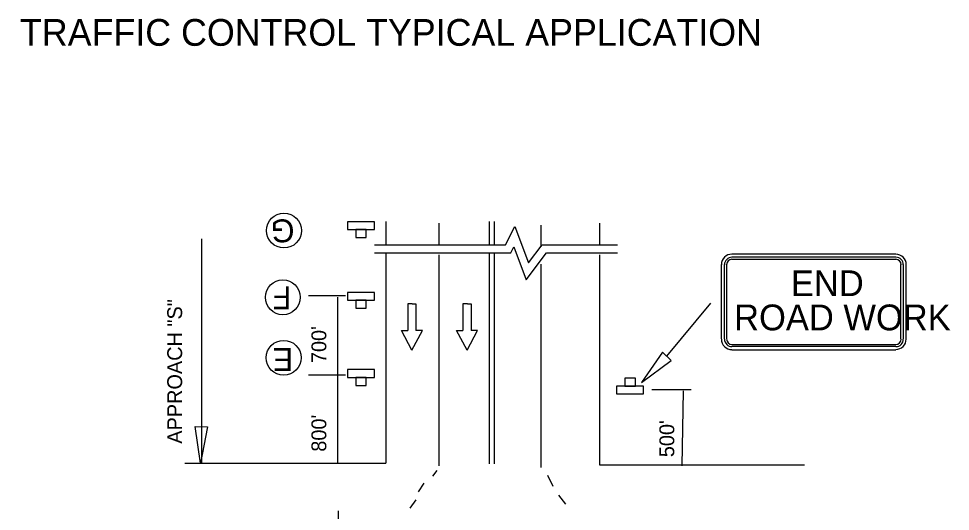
# Model space of a CAD drawing. Extents: x 1531.4 to 1538.6, y 1529.6 to 1539.6.
# Drawn here: x 1533.692 to 1537.45, y 1537.609 to 1539.597 of the extents above; entities that cross this region are included whole.
import ezdxf

# ---------------------------------------------------------------- set-up
doc = ezdxf.new("R2010")
doc.units = 0
for name, color, linetype in [('DETL-DIMS', 7, 'Continuous'), ('DETL-LINE', 7, 'Continuous'), ('DETL-NOTE', 7, 'Continuous'), ('DETL-TITL', 7, 'Continuous'), ('USER-BORD', 7, 'Continuous')]:
    doc.layers.add(name, color=color, linetype=linetype)

# ---------------------------------------------------------------- blocks, each defined once
blk = doc.blocks.new('DIR2')
at = {"layer": 'USER-BORD'}
for p, q in [((0, 0.0012), (-0.0342, -0.0477)), ((0, 0.0012), (0.0342, -0.0477)), ((-0.0342, -0.0477), (-0.0132, -0.0477)), ((-0.0132, -0.1133), (-0.0132, -0.0477)), ((0.0342, -0.0477), (0.0132, -0.0477)), ((0.0132, -0.1133), (0.0132, -0.0477)), ((-0.0011, -0.1133), (-0.0132, -0.1133)), ((-0.0011, -0.1133), (0.0011, -0.1133)), ((0.0011, -0.1133), (0.0132, -0.1133))]:
    blk.add_line(p, q, dxfattribs=at)

msp = doc.modelspace()

# ---------------------------------------------------------------- linework, layer by layer
at = {"layer": 'DETL-DIMS'}
for p, q in [((1534.4291, 1538.7082), (1534.4291, 1537.8015)), ((1535.0111, 1538.4782), (1534.8607, 1538.4782)), ((1534.9782, 1538.4735), (1534.9782, 1537.8006)), ((1536.3068, 1538.2347), (1536.4846, 1538.4491)), ((1535.0111, 1538.1583), (1534.8607, 1538.1583)), ((1536.2462, 1538.1008), (1536.4053, 1538.1008)), ((1536.3723, 1538.0957), (1536.3672, 1537.7929))]:
    msp.add_line(p, q, dxfattribs=at)
for points in [[(1536.3245, 1538.2176), (1536.2891, 1538.2518), (1536.2044, 1538.1282)], [(1534.4042, 1537.9511), (1534.4534, 1537.9501), (1534.4259, 1537.8029)]]:
    msp.add_lwpolyline(points, close=True, dxfattribs=at)
at = {"layer": 'DETL-LINE'}
for p, q in [((1535.1727, 1538.7783), (1535.1727, 1538.6847)), ((1535.3872, 1538.771), (1535.3872, 1538.6847)), ((1535.5897, 1538.7783), (1535.5897, 1538.6847)), ((1535.6101, 1538.7783), (1535.6101, 1538.6847)), ((1536.0344, 1538.771), (1536.0344, 1538.6847)), ((1535.798, 1538.7637), (1535.798, 1538.6765)), ((1535.1727, 1538.6515), (1535.1727, 1537.9889)), ((1535.3872, 1538.6442), (1535.3872, 1537.7928)), ((1535.5897, 1538.6515), (1535.5897, 1537.9889)), ((1535.6101, 1538.6515), (1535.6101, 1537.9889)), ((1536.0344, 1538.6442), (1536.0344, 1537.9816)), ((1537.2302, 1538.6464), (1536.5692, 1538.6464)), ((1537.2302, 1538.6344), (1536.5692, 1538.6344)), ((1536.5692, 1538.6264), (1537.2302, 1538.6264)), ((1537.2302, 1538.6344), (1537.2302, 1538.6344)), ((1535.798, 1538.6059), (1535.798, 1537.7856)), ((1536.5262, 1538.6044), (1536.5262, 1538.3044)), ((1536.5392, 1538.3044), (1536.5392, 1538.6044)), ((1536.5472, 1538.6044), (1536.5472, 1538.3044)), ((1537.2512, 1538.3044), (1537.2512, 1538.6044)), ((1537.2602, 1538.6044), (1537.2602, 1538.3044)), ((1537.2722, 1538.3044), (1537.2722, 1538.6044)), ((1536.5692, 1538.2824), (1537.2302, 1538.2824)), ((1536.5694, 1538.2821), (1536.5696, 1538.2827)), ((1537.2302, 1538.2744), (1536.5692, 1538.2744)), ((1536.5692, 1538.2604), (1537.2302, 1538.2604)), ((1535.1727, 1537.9974), (1535.1727, 1537.8033)), ((1535.5897, 1537.9974), (1535.5897, 1537.8002)), ((1535.6101, 1537.9974), (1535.6101, 1537.8002)), ((1536.0344, 1537.9901), (1536.0344, 1537.796)), ((1534.3621, 1537.8033), (1535.1727, 1537.8033)), ((1536.0344, 1537.796), (1536.862, 1537.796)), ((1535.3791, 1537.7744), (1535.3616, 1537.7511)), ((1535.8253, 1537.7544), (1535.8472, 1537.7106)), ((1535.3267, 1537.722), (1535.3035, 1537.6871)), ((1535.2938, 1537.656), (1535.2705, 1537.6211)), ((1535.869, 1537.6742), (1535.8981, 1537.6378)), ((1534.9823, 1536.8051), (1534.9823, 1537.6108))]:
    msp.add_line(p, q, dxfattribs=at)
for points in [[(1535.127, 1538.7459), (1535.127, 1538.7772), (1535.0179, 1538.7772), (1535.0179, 1538.7459)], [(1535.0515, 1538.7134), (1535.0935, 1538.7134), (1535.0935, 1538.7459), (1535.0515, 1538.7459)], [(1535.127, 1538.4609), (1535.127, 1538.4922), (1535.0179, 1538.4922), (1535.0179, 1538.4609)], [(1535.0515, 1538.4284), (1535.0935, 1538.4284), (1535.0935, 1538.4609), (1535.0515, 1538.4609)], [(1535.127, 1538.1496), (1535.127, 1538.1809), (1535.0179, 1538.1809), (1535.0179, 1538.1496)], [(1535.0515, 1538.1171), (1535.0935, 1538.1171), (1535.0935, 1538.1496), (1535.0515, 1538.1496)], [(1536.1797, 1538.1468), (1536.1377, 1538.1468), (1536.1377, 1538.1143), (1536.1797, 1538.1143)], [(1536.1042, 1538.1143), (1536.1042, 1538.083), (1536.2132, 1538.083), (1536.2132, 1538.1143)]]:
    msp.add_lwpolyline(points, close=True, dxfattribs=at)
for points in [[(1535.1273, 1538.6847), (1535.6564, 1538.6847), (1535.6935, 1538.7579), (1535.7489, 1538.6114), (1535.8043, 1538.6847), (1536.1074, 1538.6847)], [(1535.1273, 1538.6515), (1535.6768, 1538.6515), (1535.6891, 1538.6757), (1535.739, 1538.5434), (1535.8208, 1538.6515), (1536.1074, 1538.6515)], [(1535.3872, 1538.4942), (1535.3872, 1538.3942)], [(1535.798, 1538.4559), (1535.798, 1538.3559)], [(1535.3872, 1538.0942), (1535.3872, 1537.9942)], [(1535.798, 1538.0559), (1535.798, 1537.9559)]]:
    msp.add_lwpolyline(points, dxfattribs=at)
for centre in [(1534.7622, 1538.7419), (1534.7577, 1538.4726), (1534.7609, 1538.2285)]:
    msp.add_circle(centre, 0.0704, dxfattribs=at)
for centre, radius, start, end in [((1536.5694, 1538.6042), 0.0424, 90, 180), ((1536.5694, 1538.6042), 0.0301, 90, 180), ((1536.5694, 1538.6042), 0.0216, 90, 180), ((1537.2306, 1538.6042), 0.0421, 0, 90), ((1537.2306, 1538.6042), 0.0301, 0, 90), ((1537.2306, 1538.6042), 0.0216, 0, 90), ((1536.5694, 1538.3037), 0.0424, 180, 270), ((1536.5694, 1538.3037), 0.0301, 180, 270), ((1536.5694, 1538.3037), 0.0216, 180, 270), ((1537.2306, 1538.3037), 0.0415, 270, 0), ((1537.2306, 1538.3037), 0.0216, 270, 0), ((1537.2306, 1538.3037), 0.0301, 270, 0)]:
    msp.add_arc(centre, radius, start, end, dxfattribs=at)

# ---------------------------------------------------------------- block references
at = {"layer": 'DETL-LINE', "xscale": 1.2309405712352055, "yscale": 1.641254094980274, "rotation": 180}
for p in [(1535.2785, 1538.2608), (1535.5006, 1538.2608)]:
    msp.add_blockref('DIR2', p, dxfattribs=at)

# ---------------------------------------------------------------- texts
at = {"layer": 'DETL-LINE'}
for s, height, rotation, p in [('G', 0.0924, 180, (1534.8047, 1538.7869)), ('END', 0.1041, 360, (1536.8071, 1538.4773)), ('F', 0.0924, 180, (1534.7919, 1538.517)), ('ROAD WORK', 0.1041, 360, (1536.5781, 1538.3393)), ('E', 0.0924, 180, (1534.7987, 1538.2676))]:
    msp.add_text(s, height=height, rotation=rotation, dxfattribs=at).set_placement(p)
at = {"layer": 'DETL-NOTE'}
for s, p in [('APPROACH "S"', (1534.3514, 1537.8818)), ("700'", (1534.933, 1538.2071)), ("800'", (1534.933, 1537.8496)), ("500'", (1536.3367, 1537.8275))]:
    msp.add_text(s, height=0.06, rotation=90, dxfattribs=at).set_placement(p)
at = {"layer": 'DETL-TITL'}
msp.add_text('TEMPORARY TRAFFIC CONTROL TYPICAL APPLICATION', height=0.108, dxfattribs=at).set_placement((1532.7424, 1539.4873))

doc.saveas('drawing.dxf')
